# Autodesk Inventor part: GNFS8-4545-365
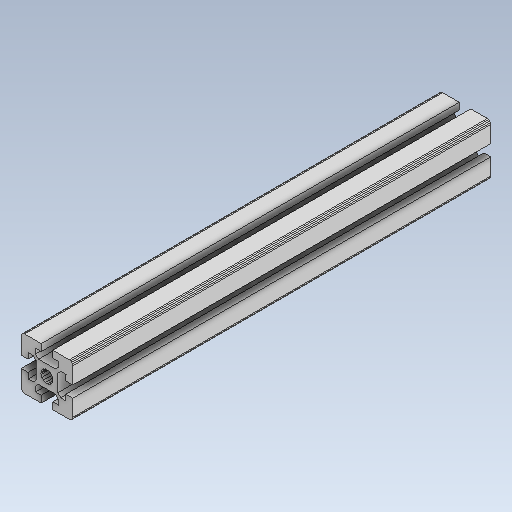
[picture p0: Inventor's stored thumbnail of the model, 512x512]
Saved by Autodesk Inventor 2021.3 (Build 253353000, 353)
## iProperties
Created: 2022-02
Part Number: GNFS8-4545-365
Material: 一般
Document SubType Name: Modeling
Designer: kengo
Density: 1 g/cm^3
Appearance: 既定
Author: kengo
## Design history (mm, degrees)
feature "GNFS8-4545-365"
node "ソリッド1"
